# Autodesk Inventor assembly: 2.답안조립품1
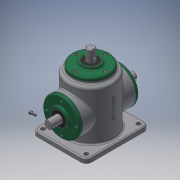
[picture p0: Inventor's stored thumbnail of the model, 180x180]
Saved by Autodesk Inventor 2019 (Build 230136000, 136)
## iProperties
Created: 2020-12
Part Number: 2.답안조립품1
Material: 일반
Document SubType Name: Assembly
Designer: jun-1-2
Author: jun-1-2
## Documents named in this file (16)
- C:\Users\jun-1-2\Desktop\701207V1009\2.답안조립품1.iam
- C:\Users\jun-1-2\Desktop\701207V1009\1.본체.ipt
- C:\Users\jun-1-2\Desktop\701207V1009\메인 베벨기어.ipt
- C:\Users\jun-1-2\Desktop\701207V1009\메인 축.ipt
- 메인 축.ipt
- C:\Users\jun-1-2\Desktop\701207V1009\베어링 6203.ipt
- C:\Users\jun-1-2\Desktop\701207V1009\볼트 M4.ipt
- 볼트 M4.ipt
- C:\Users\jun-1-2\Desktop\701207V1009\서브 베벨기어.ipt
- C:\Users\jun-1-2\Desktop\701207V1009\서브 축.ipt
- 서브 축.ipt
- C:\Users\jun-1-2\Desktop\701207V1009\오일 실.ipt
- 오일 실.ipt
- C:\Users\jun-1-2\Desktop\701207V1009\커버.ipt
- C:\Users\jun-1-2\Desktop\701207V1009\키 4x4.ipt
- C:\Users\jun-1-2\Desktop\701207V1009\키 5x5.ipt
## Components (1 placed, 1 different names)
1. 1.본체:1
